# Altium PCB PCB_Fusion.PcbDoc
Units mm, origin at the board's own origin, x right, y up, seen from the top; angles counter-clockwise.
Board outline 25.02 x 45.09 mm, 2 copper layers (Top Layer, Bottom Layer); 48 components, 36 nets, 184 pads, 53 vias.
Unrouted connection lines stored in the file: 1.
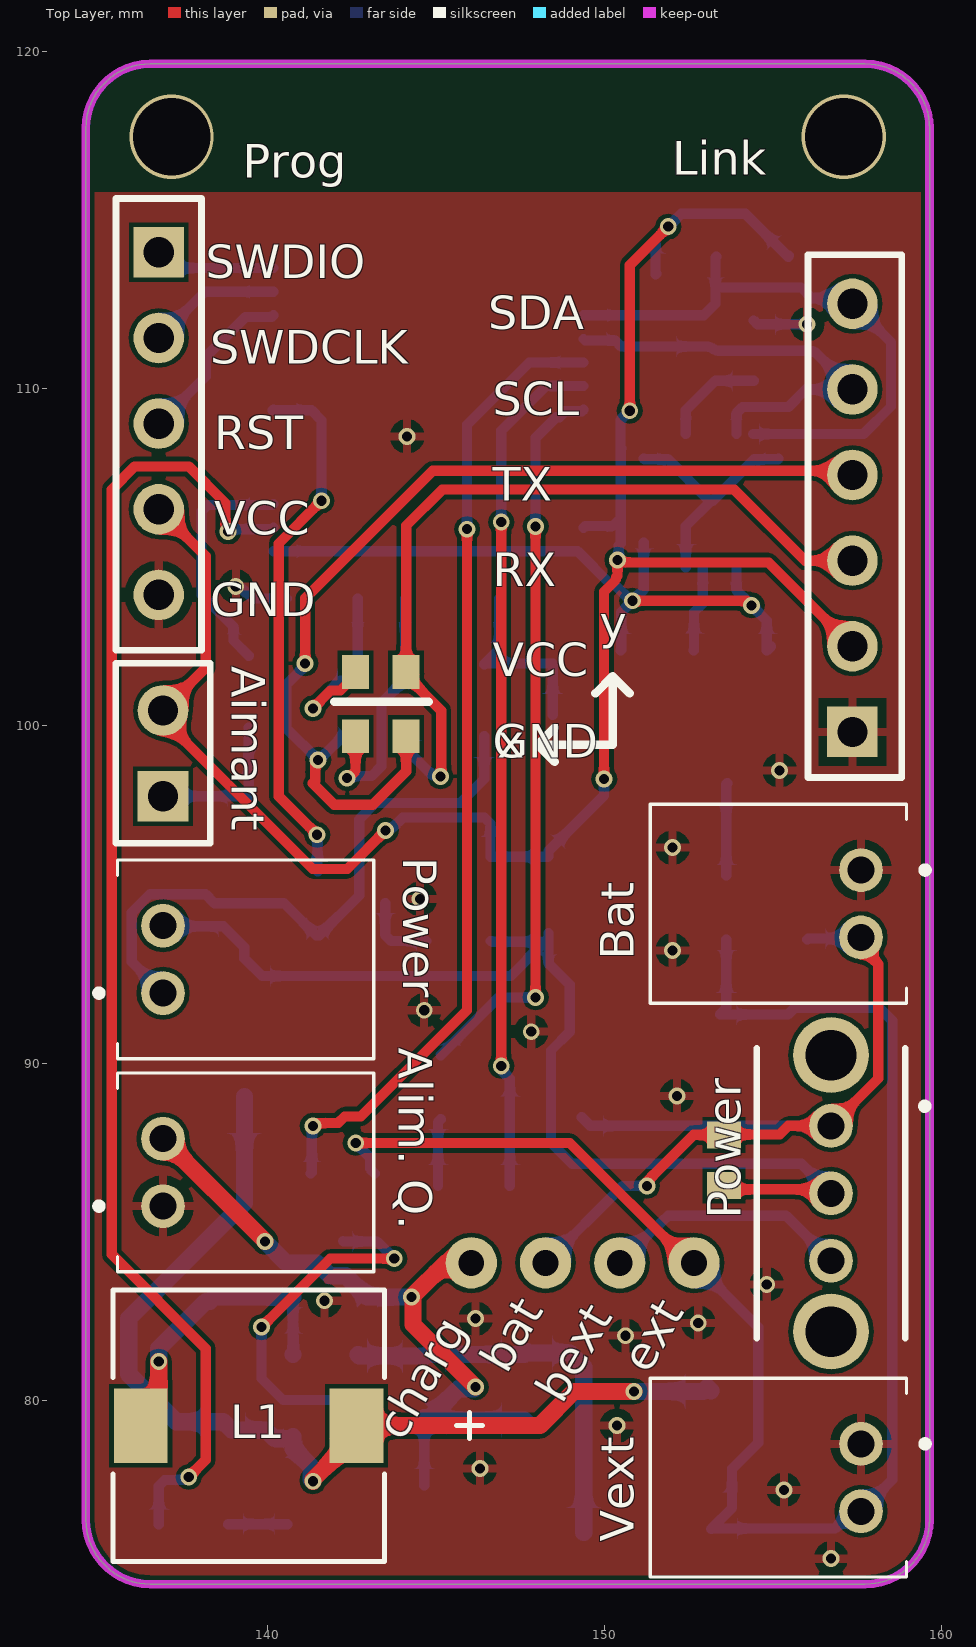
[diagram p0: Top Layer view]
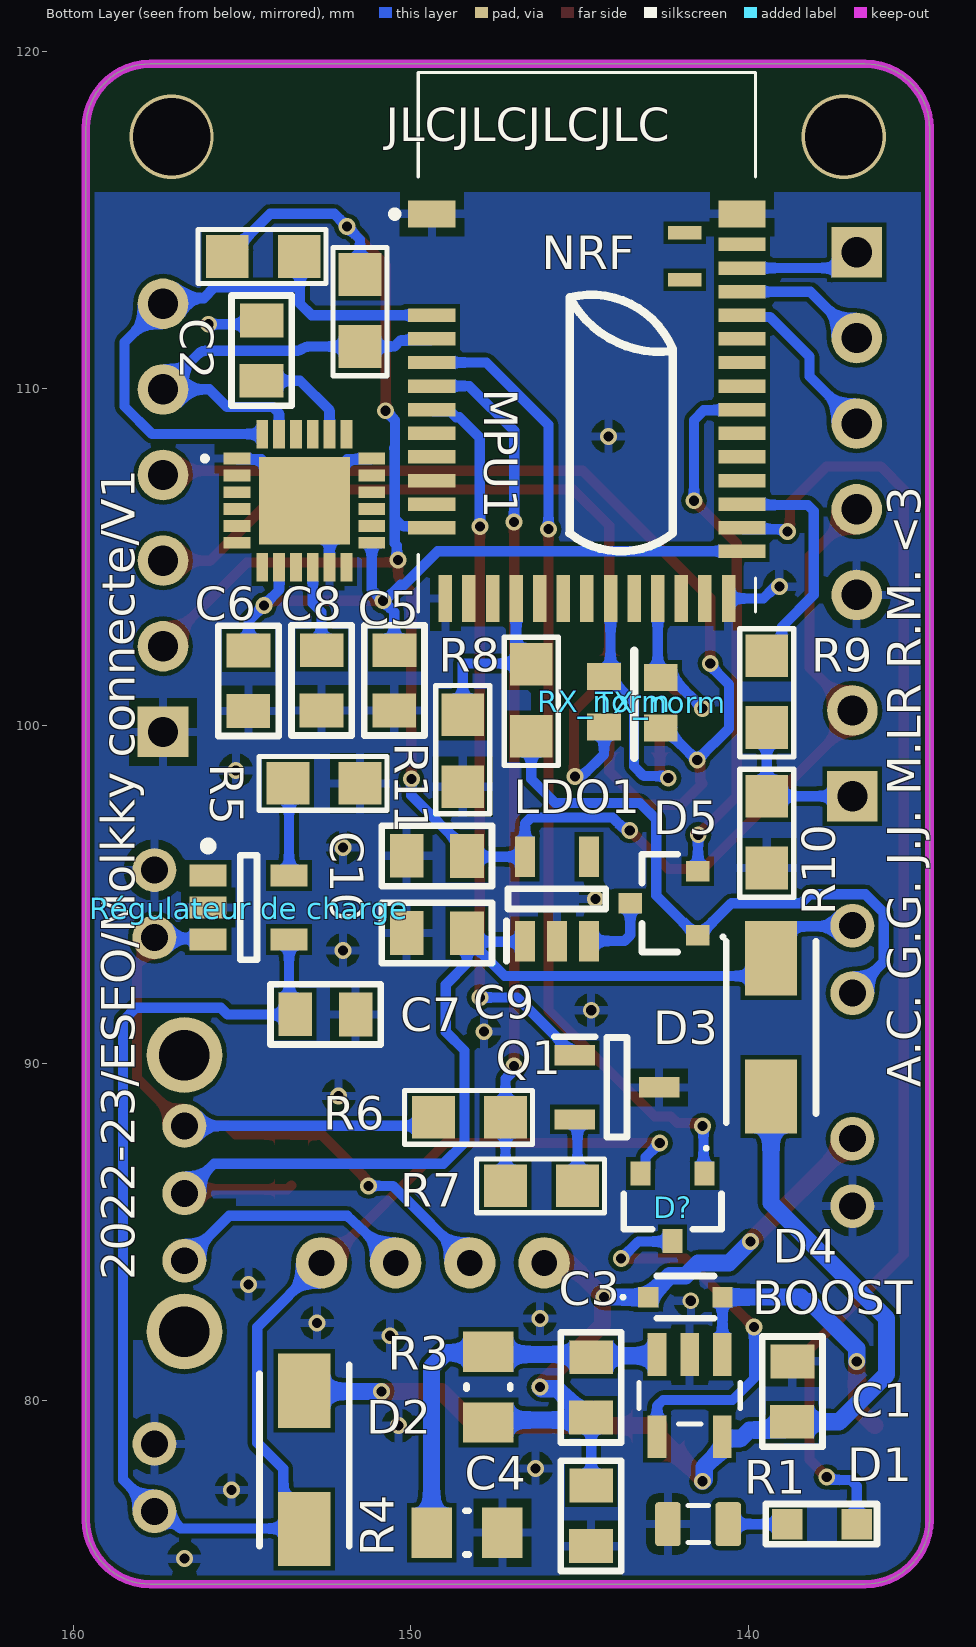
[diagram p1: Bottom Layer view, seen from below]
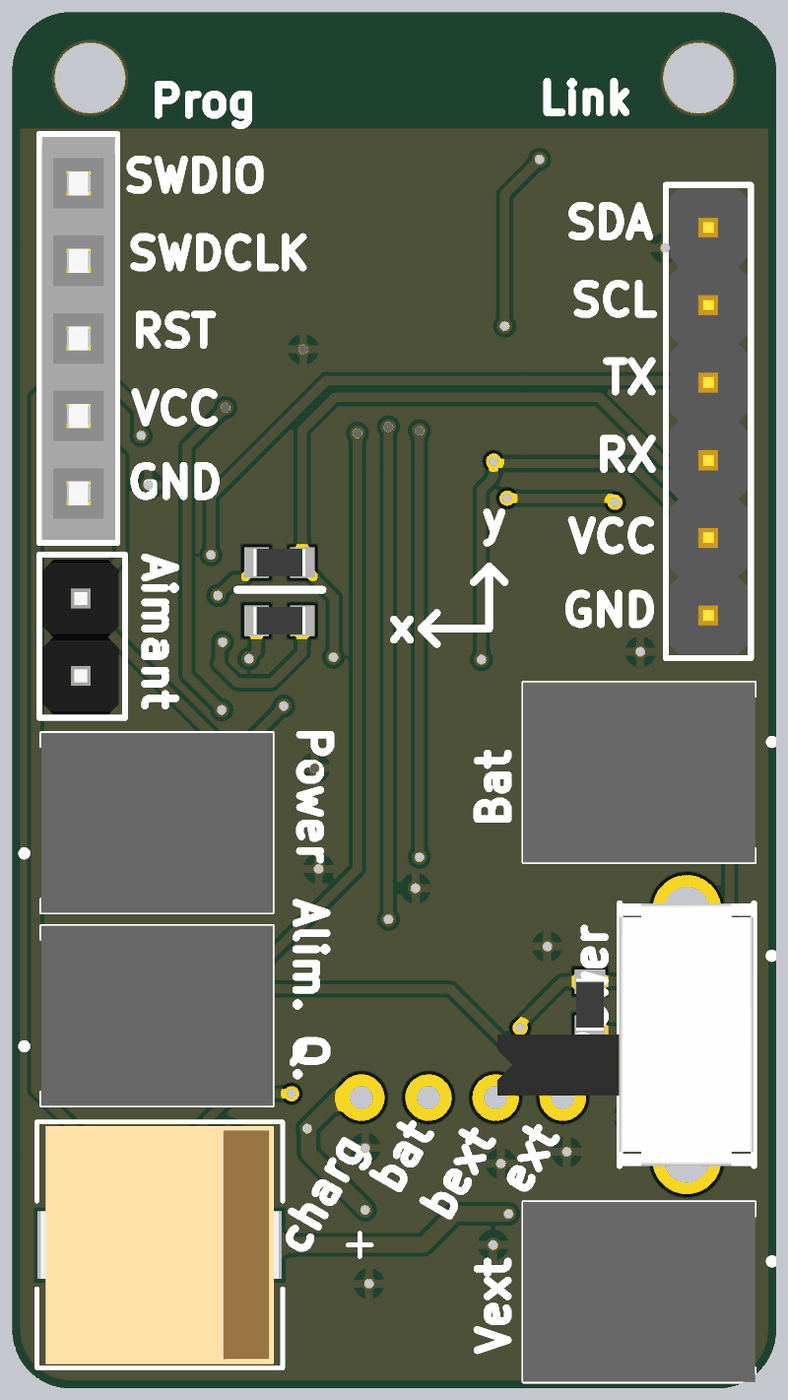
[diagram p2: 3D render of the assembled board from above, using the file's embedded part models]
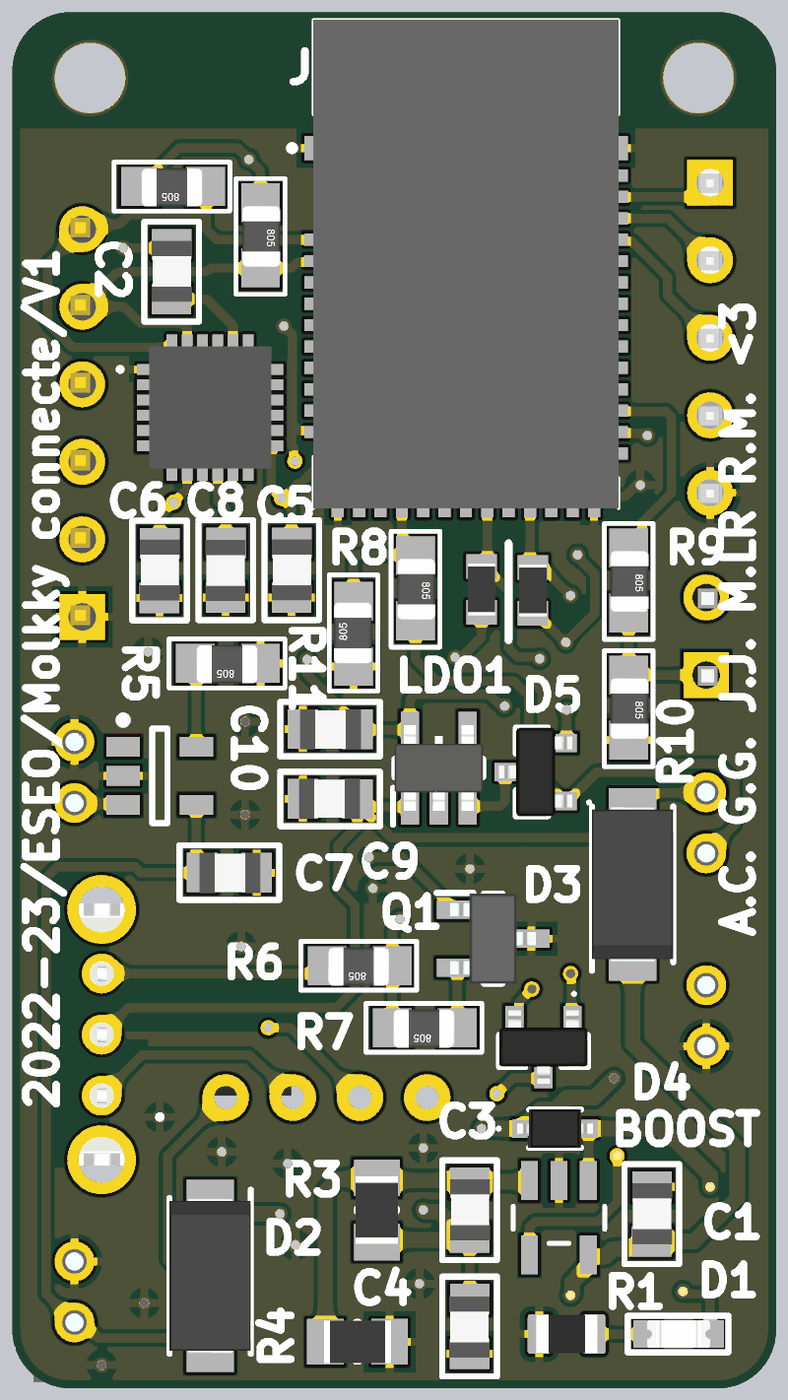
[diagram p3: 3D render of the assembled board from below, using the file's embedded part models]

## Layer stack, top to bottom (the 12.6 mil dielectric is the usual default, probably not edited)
Top Solder: solder mask 0.0102, Solder Resist, Dk 3.5
Top Layer: signal copper 0.0356
Dielectric 1: dielectric 0.32, FR-4, Dk 4.8
Bottom Layer: signal copper 0.0356
Bottom Solder: solder mask 0.0102, Solder Resist, Dk 3.5

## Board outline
134.62,76.454 134.62,117.729 cw(c136.525,117.729) 136.525,119.634 157.734,119.634 cw(c157.734,117.729) 159.639,117.729 159.639,76.454 cw(c157.734,76.454) 157.734,74.549 136.525,74.549 cw(c136.525,76.454)

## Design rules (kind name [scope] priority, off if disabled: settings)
Clearance [All] p1: gap=0.127 ignorepadtopadclearanceinfootprint=FALSE except(0.254: Arc-Via Track-Via Via-Via; 0.508: THPad-THPad)
PolygonConnect [All] p1: connectstyle=Relief reliefconductorwidth=0.254 reliefentries=4 polygonreliefangle="90 Angle" airgapwidth=0.254
RoutingVias [All] p1: holewidth=0.3 width=0.5 viastyle="Through Hole" minholewidth=0.762 minwidth=0.381 maxholewidth=1.016 maxwidth=0.762
SMDNeckDown [All] p1: percent=50.000
SolderMaskExpansion [All] p1: expansion=0.102 istentingtop=FALSE
Width [All] p1: maxlimit=0.508 minlimit=0.127 preferedwidth=0.305
30 further rules are at their usual default settings.

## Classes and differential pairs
component class Fusion: BOOST C1 C2 C3 C4 C5 C6 C7 C8 C9 C10 D1 D2 D3 D4 D5 L1 LDO1 Link MPU1 NRF Prog Q1 R1 R3 R4 R5 R6 R7 R8 R9 R10 R11

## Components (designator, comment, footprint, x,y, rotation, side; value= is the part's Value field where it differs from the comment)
Aimant "JUMPER2" BARRETTE_2_M_D 136.906,97.917 r90 top (schematic designator "Switch magnetique1")
"Alim. Q." "S2B-PH-K-S" S2BPHKS 136.906,85.757 r270 top (schematic designator Connecteur_Alim_Quille1)
Bat "S2B-PH-K-S" S2BPHKS 157.607,95.726 r90 top (schematic designator "Connecteur Bat")
BOOST "LM2735XMF" SOT95P285X110-5N 141.732,80.137 r270 bottom
C1 "CONDENSATEUR_CMS_CER_0805" CONDENSATEUR_CMS_0805 138.694,79.363 r90 bottom value=10uF
C2 "CONDENSATEUR_CMS_CER_0805" CONDENSATEUR_CMS_0805 154.432,110.236 r90 bottom value=2.2nF
C3 "CONDENSATEUR_CMS_CER_0805" CONDENSATEUR_CMS_0805 144.663,79.49 r90 bottom value=330pF
C4 "CONDENSATEUR_CMS_CER_0805" CONDENSATEUR_CMS_0805 144.653,77.47 r270 bottom value=10uF
C5 "CONDENSATEUR_CMS_CER_0805" CONDENSATEUR_CMS_0805 150.495,100.457 r90 bottom value=100nF
C6 "CONDENSATEUR_CMS_CER_0805" CONDENSATEUR_CMS_0805 154.823,100.445 r90 bottom value=10nF
C7 "CONDENSATEUR_CMS_CER_0805" CONDENSATEUR_CMS_0805 153.428,91.45 r180 bottom value=4.7uF
C8 "CONDENSATEUR_CMS_CER_0805" CONDENSATEUR_CMS_0805 152.644,102.247 r270 bottom value=100nF
C9 "CONDENSATEUR_CMS_CER_0805" CONDENSATEUR_CMS_0805 148.336,93.853 r0 bottom value=1uF
C10 "CONDENSATEUR_CMS_CER_0805" CONDENSATEUR_CMS_0805 150.126,96.149 r180 bottom value=4.7uF
D1 "LED_CMS_0805" LED_CMS_0805 136.779,76.327 r270 bottom
D2 "ES1D-E3_61T" DIOM5127X229N 153.162,78.232 r270 bottom
D3 "ES1D-E3_61T" DIOM5127X229N 139.319,91.059 r90 bottom
D4 "BAT165AX" BAT165AX 141.859,83.058 r180 bottom
D5 "BAT54C,215" BAT54C215 142.494,94.742 r90 bottom
D? "BAT54C,215" BAT54C215 142.24,85.725 r0 bottom
L1 "1234659" IND_123_4659_RSP 139.446,79.248 r180 top
LDO1 "TPS76333DBVT" SOT95P280X145-5N 145.669,94.869 r90 bottom
Link "BARRETTE_6 CONTACTS_1 RANGEE_MALE_DROITE" BARRETTE_6_M_D 157.353,99.822 r90 top (schematic designator "Connecteur link")
MPU1 "MPU-6050" MPU6050 153.162,106.68 r180 bottom
NRF "MDBT42Q-512KV2" MDBT42Q512KV2 144.78,111.379 r180 bottom
Power "OS102011MA1QN1" OS102011MA1QN1 156.718,86.138 r270 top (schematic designator "Interrupteur glissière?")
Power "S2B-PH-K-S" S2BPHKS 136.906,92.075 r270 top (schematic designator "Interrupteur Power")
Prog "BARRETTE_5 CONTACTS_1 RANGEE_FEMELLE_DROITE" BARRETTE_5_F_D 136.779,114.046 r270 top (schematic designator "Connecteur prog1")
"PULLUP SCL1" "RESISTANCE_CMS_0805" RESISTANCE_CMS_0805 151.511,113.386 r270 bottom value=10k
"PULLUP SDA1" "RESISTANCE_CMS_0805" RESISTANCE_CMS_0805 153.314,113.919 r0 bottom value=10k
Q1 "TSM2312CX_RFG" SOT95P280X130-3N 143.891,89.281 r180 bottom
R1 "Resistor 1K +/-5% 0805 125 mW" RESC0805(2012)_L 141.478,76.327 r180 bottom value=150
R2 "Resistor 4k7 +/-1% 0603 100 mW" RESC1608X55X25ML10T15 153.543,87.122 r270 top value=0
R3 "Resistor 10k +/-1% 0805 125 mW" RESC2013X50X35ML15T15 147.701,80.391 r270 bottom value=3.3k
R4 "Resistor 10k +/-1% 0805 125 mW" RESC2013X50X35ML15T15 148.336,76.073 r0 bottom value=10k
R5 "RESISTANCE_CMS_0805" RESISTANCE_CMS_0805 151.511,98.298 r0 bottom value=10k
R6 "RESISTANCE_CMS_0805" RESISTANCE_CMS_0805 147.193,88.392 r0 bottom value=100k
R7 "RESISTANCE_CMS_0805" RESISTANCE_CMS_0805 145.059,86.36 r0 bottom value=100k
R8 "RESISTANCE_CMS_0805" RESISTANCE_CMS_0805 146.431,101.829 r270 bottom value=100k
R9 "RESISTANCE_CMS_0805" RESISTANCE_CMS_0805 139.446,102.083 r270 bottom value=100
R10 "RESISTANCE_CMS_0805" RESISTANCE_CMS_0805 139.446,97.917 r270 bottom value=10k
R11 "RESISTANCE_CMS_0805" RESISTANCE_CMS_0805 148.463,98.196 r90 bottom value=100k
RX_inv "Resistor 4k7 +/-1% 0603 100 mW" RESC1608X55X25ML10T15 143.367,99.695 r0 top value=0
RX_norm "Resistor 4k7 +/-1% 0603 100 mW" RESC1608X55X25ML10T15 144.272,100.723 r90 bottom value=0
"Régulateur de charge" "MCP73831T-2DCI/OT" SOT-23-OT5_N 154.813,94.615 r180 bottom
TX_inv "Resistor 4k7 +/-1% 0603 100 mW" RESC1608X55X25ML10T15 143.367,101.6 r0 top value=0
TX_norm "Resistor 4k7 +/-1% 0603 100 mW" RESC1608X55X25ML10T15 142.587,100.689 r90 bottom value=0
Vext "S2B-PH-K-S" S2BPHKS 157.607,78.708 r90 top (schematic designator "Connecteur Vext")

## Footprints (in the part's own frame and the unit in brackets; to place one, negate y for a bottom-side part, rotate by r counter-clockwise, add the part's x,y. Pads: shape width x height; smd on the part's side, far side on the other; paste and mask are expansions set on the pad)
BARRETTE_2_M_D [mm] "BARRETTE 2 CONTACTS ; 1 RANGEE ; DROITE ; MALE ; ESPACEMENT BROCHES = 2.54 mm"
  rect 1.5x1.5 hole 0.9: 1(0,0)
  round 1.5 hole 0.9: 2(2.54,0)
  silkscreen extent -1.4,-1.4 3.94,1.4, body extent -1.3,-1.2 3.78,1.3, height 8.55
BARRETTE_5_F_D [mm] "BARRETTE 5 CONTACTS ; 1 RANGEE ; DROITE ; FEMELLE ; ESPACEMENT BROCHES = 2.54 mm"
  rect 1.5x1.5 hole 0.9: 1(0,0)
  round 1.5 hole 0.9: 2(2.54,0) 3(5.08,0) 4(7.62,0) 5(10.16,0)
  silkscreen extent -1.6,-1.27 11.8,1.27, body extent -1.5,-1.2 11.7,1.21, height 8.5
BARRETTE_6_M_D [mm] "BARRETTE 6 CONTACTS ; 1 RANGEE ; DROITE ; MALE ; ESPACEMENT BROCHES = 2.54 mm"
  rect 1.5x1.5 hole 0.9: 1(0,0)
  round 1.5 hole 0.9: 2(2.54,0) 3(5.08,0) 4(7.62,0) 5(10.16,0) 6(12.7,0)
  silkscreen extent -1.35,-1.46 14.15,1.32, body extent -1.22,-1.34 14.02,1.2, height 10.1
BAT54C215 [mm]
  rect 0.6x0.7 smd: 1(-0.95,-1) 2(0.95,-1) 3(0,1)
  silkscreen extent -1.45,-1.8 1.45,0.65, body extent -1.45,-1.2 1.45,1.2, height 0.95
BAT165AX [mm]
  rect 0.6x0.6 smd: 1(-1.1,0) 2(1.1,0)
  silkscreen extent -1.9,-0.62 0.85,0.62, body extent -1.24,-0.62 1.24,0.63, height 0.93
CONDENSATEUR_CMS_0805 [mm] "CONDENSATEUR CMS 0805 ; DIMENSIONS : 2mm x 1.25mm"
  rect 1x1.3 smd: 1(0,0) 2(1.79,-0.01)
  silkscreen extent -0.74,-0.9 2.53,0.89, body extent -0.09,-0.67 1.91,0.64, height 0.73
DIOM5127X229N [mm]
  rect 2.2x1.55 smd: 1(-2.05,0) 2(2.05,0)
  silkscreen extent -2.82,-1.33 2.55,1.33, body extent -2.55,-1.33 2.55,1.33, height 2.29
IND_123_4659_RSP [mil]
  rect 63x87 smd paste+0 mask+0: 1(-126,0) 2(126,0)
  silkscreen extent -273,-159 159,159, body extent -154,-154 154,154, height 199
LED_CMS_0805 [mm] "LED CMS 0805 ; DIMENSIONS : 2.0mm x 0.9mm"
  rect 0.9x0.9 smd: 1(0,0) 2(0,-2.062)
  silkscreen extent -0.6,-2.7 0.6,0.6, body extent -0.45,-2.06 0.45,0, height 0.85
MDBT42Q512KV2 [mm]
  rect 1.4x0.8 smd: 1(-4.6,3.8) 39(4.6,3.8)
  rect 1.4x0.4 smd: 2(-4.6,0.8) 3(-4.6,0.1) 4(-4.6,-0.6) 5(-4.6,-1.3) 6(-4.6,-2) 7(-4.6,-2.7) 8(-4.6,-3.4) 9(-4.6,-4.1) 10(-4.6,-4.8) 11(-4.6,-5.5) 25(4.6,-6.2) 26(4.6,-5.5) 27(4.6,-4.8) 28(4.6,-4.1) 29(4.6,-3.4) 30(4.6,-2.7) 31(4.6,-2) 32(4.6,-1.3) 33(4.6,-0.6) 34(4.6,0.1) 35(4.6,0.8) 36(4.6,1.5) 37(4.6,2.2) 38(4.6,2.9)
  rect 0.4x1.4 smd: 12(-4.2,-7.6) 13(-3.5,-7.6) 14(-2.8,-7.6) 15(-2.1,-7.6) 16(-1.4,-7.6) 17(-0.7,-7.6) 18(0,-7.6) 19(0.7,-7.6) 20(1.4,-7.6) 21(2.1,-7.6) 22(2.8,-7.6) 23(3.5,-7.6) 24(4.2,-7.6)
  rect 1x0.4 smd: 40(2.9,3.25) 41(2.9,1.85)
  silkscreen extent -5.8,-8 5,8, body extent -5,-8 5,8, height 2.3
MPU6050 [mm]
  rect 0.8x0.35 smd: 1(-2,1.25) 2(-2,0.75) 3(-2,0.25) 4(-2,-0.25) 5(-2,-0.75) 6(-2,-1.25) 13(2,-1.25) 14(2,-0.75) 15(2,-0.25) 16(2,0.25) 17(2,0.75) 18(2,1.25)
  rect 0.35x0.85 smd: 7(-1.25,-1.975) 8(-0.75,-1.975) 9(-0.25,-1.975) 10(0.25,-1.975) 11(0.75,-1.975) 12(1.25,-1.975) 19(1.25,1.975) 20(0.75,1.975) 21(0.25,1.975) 22(-0.25,1.975) 23(-0.75,1.975) 24(-1.25,1.975)
  rect 2.7x2.6 smd: 25(0,0)
  silkscreen extent -3,1.2 -2.9,1.3, body extent -2,-2 2,2, height 0.88
OS102011MA1QN1 [mm]
  round 1.3 hole 0.8: 1(-2,0) 2(0,0) 3(2,0)
  round 2.25 hole 1.5: 4(-4.1,0) 5(4.1,0)
  silkscreen extent -4.3,-2.2 4.3,2.88, body extent -4.3,-6.22 4.3,2.18, height 4.59
RESC0805(2012)_L [mm] "Chip Resistor, Body 2.0x1.3mm, IPC High Density"
  rrect25% 0.76x1.3 smd: 1(-0.9,0) 2(0.89,0)
  silkscreen extent -0.3,-0.55 0.3,0.55, body extent -1,-0.62 1,0.63, height 0.6
RESC1608X55X25ML10T15 [mm] "Chip Resistor, 2-Leads, Body 1.70x0.90mm, IPC Low Density"
  rect 0.8x1 smd: 1(-0.75,0) 2(0.75,0)
  body extent -0.85,-0.45 0.85,0.45, height 0.55
RESC2013X50X35ML15T15 [mm] "Chip Resistor, 2-Leads, Body 2.2x1.4mm, IPC Low Density"
  rect 1.2x1.5 smd: 1(-1.05,0) 2(1.05,0)
  silkscreen extent -0.05,-0.65 0.05,0.65, body extent -1.1,-0.7 1.1,0.7, height 0.5
RESISTANCE_CMS_0805 [mil] "RESISTANCE CMS 0805 ; DIMENSIONS : 2mm x 1.25mm"
  rect 50x50 smd: 1(0,0) 2(84,0)
  silkscreen extent -31,-31 118,31, body extent 4,-24 83,26, height 31
S2BPHKS [mm]
  round 1.3 hole 0.8: 1(0,0) 2(-2,0)
  silkscreen extent -3.95,-2 1.95,6.25, body extent -3.95,-1.35 1.95,6.25, height 4.9
SOT95P280X130-3N [mm]
  rect 1.2x0.6 smd: 1(-1.25,0.95) 2(-1.25,-0.95) 3(1.25,0)
  silkscreen extent -1.85,-1.47 0.3,1.5, body extent -1.4,-1.47 1.4,1.47, height 1.3
SOT95P280X145-5N [mm]
  rect 1.2x0.6 smd: 1(-1.25,0.95) 2(-1.25,0) 3(-1.25,-0.95) 4(1.25,-0.95) 5(1.25,0.95)
  silkscreen extent -1.85,-1.45 0.3,1.5, body extent -1.4,-1.45 1.4,1.45, height 1.2
SOT95P285X110-5N [mil]
  rect 50x22 smd: 1(-48,38) 2(-48,0) 3(-48,-38) 4(48,-38) 5(48,38)
  silkscreen extent -15,-59 33,59
SOT-23-OT5_N [mm] "SOT23, 5-Leads, Body 2.9x1.6mm, Pitch 0.95mm, Lead Span 2.7mm, IPC Medium Density"
  rect 1.1x0.65 smd: 1(-1.2,0.95) 2(-1.2,0) 3(-1.2,-0.95) 4(1.2,-0.95) 5(1.2,0.95)
  silkscreen extent -1.33,-1.55 0.25,1.95, body extent -0.9,-1.55 0.9,1.55, height 1.45

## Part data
Aimant: library part CMP-039-0004-1, "BARRETTE 2 CONTACTS 1 RANGEE MALE DROITE"
"Alim. Q." Bat Power Vext: "Connector", Manufacturer_Name="JST (JAPAN SOLDERLESS TERMINALS)"
BOOST: "Integrated Circuit", Manufacturer_Name="Texas Instruments"
C1 C2 C3 C4 C5 C6 C7 C8 C9 C10: library part CMP-038-0003-1, "CONDENSATEUR CMS CERAMIQUE 0805"
D1: library part CMP-024-0003-1, "LED CMS 0805"
D2 D3: "Diode", Arrow Part Number=ES1D-E3/61T, Manufacturer_Name=Vishay, Mouser Part Number=625-ES1D-E3
D4: "Schottky Diode", Manufacturer_Name=Nexperia, Mouser Part Number=771-BAT165AX
D5 D?: "Schottky Diode", Manufacturer_Name=Nexperia, Mouser Part Number=771-BAT54C-T/R
L1: "No Description Available", Mfr_Name="RS Pro"
LDO1: "Integrated Circuit", Manufacturer_Name="Texas Instruments", Mouser Part Number=595-TPS76333DBVT
Link: library part CMP-039-0125-1, "BARRETTE 6 CONTACTS 1 RANGEE MALE DROITE"
MPU1: "Integrated Circuit", Manufacturer_Name=TDK, Mouser Part Number=410-MPU-6050
NRF: "Integrated Circuit", Manufacturer_Name=Raytac
Power: "Switch", Manufacturer_Name="C & K COMPONENTS", Mouser Part Number=611-OS102011MA1QN1
Prog: library part CMP-039-0118-1, "BARRETTE 5 CONTACTS 1 RANGEE FEMELLE DROITE"
"PULLUP SCL1" "PULLUP SDA1" R5 R6 R7 R8 R9 R10 R11: library part CMP-037-0001-1, "RESISTANCE CMS 0805"
Q1: "MOSFET (N-Channel)", Arrow Part Number="TSM2312CX RFG", Manufacturer_Name="Taiwan Semiconductor", Mouser Part Number=821-TSM2312CXRFG
R1: library part CMP-009-00118-3, "Chip Resistor, 1 kOhms, +/-5%, 125 mW, -55 to 155 degC, 0805", Case/Package=0805, Max Operating Temperature=155°C, Min Operating Temperature=-55°C, Power=125mW, Tolerance=5%
R2 RX_inv RX_norm TX_inv TX_norm: library part CMP-009-00031-5, "Chip Resistor, 4.7 KOhm, +/- 1%, 0.1 W, -55 to 155 degC, 0603 (1608 Metric)", Case/Package=0603, Max Operating Temperature=155°C, Min Operating Temperature=-55°C, Power=100mW, Tolerance=1%
R3 R4: library part CMP-009-00018-5, "Chip Resistor, 10 KOhm, +/- 1%, 125 mW, -55 to 155 degC, 0805 (2012 Metric)", Case/Package=0805, Max Operating Temperature=155°C, Min Operating Temperature=-55°C, Power=125mW, Tolerance=1%, Voltage Rating=150V
"Régulateur de charge": library part CMP-045-0000-1, "Miniature Single-Cell, Fully Integrated Li-Ion, Li-Polymer Charge Management Controller, 4.2V, 5-Pin SOT-23, Industrial Temperature, Tape and Reel", Manufacturer=Microchip

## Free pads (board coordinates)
  round 1.524 hole 0.762: 2(150.453,84.074) 3(148.251,84.074) 5(146.05,84.074) 6(152.654,84.074)

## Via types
v1: diameter 0.5, hole 0.3, Top Layer to Bottom Layer, 51 vias
v2: diameter 2.5, hole 2.3, Top Layer to Bottom Layer, 2 vias

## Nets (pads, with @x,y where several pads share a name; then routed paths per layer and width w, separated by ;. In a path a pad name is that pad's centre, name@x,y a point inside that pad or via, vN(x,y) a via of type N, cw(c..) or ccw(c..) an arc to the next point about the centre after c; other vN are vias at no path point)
Aimant: NRF.27 R9.1 | length 7.1
  Bottom Layer w0.305: R9.1 138.996,102.533 138.996,102.939 138.049,103.886 138.049,106.374 138.228,106.553 140.154,106.553 NRF.27
"EN lecture bat": NRF.6 Q1.1 | length 21.9
  Top Layer w0.305: v1(147.955,91.948) v1(147.955,105.918)
  Bottom Layer w0.305: Q1.1 146.858,91.948 v1(147.955,91.948) ; v1(147.955,105.918) 147.955,108.549 148.564,109.158 148.659,109.158 148.832,109.331 149.332,109.331 NRF.6
EN_Alim_quilles: D?.1 NRF.4 | length 29
  Top Layer w0.305: v1(141.351,88.138) 141.438,88.225 142.103,88.225 142.295,88.417 142.773,88.417 145.923,91.567 v1(145.923,105.835)
  Bottom Layer w0.305: D?.1 141.32,86.756 141.32,88.107 v1(141.351,88.138) ; v1(145.923,105.835) 145.923,108.937 147.765,110.779 NRF.4
GND: "Alim. Q..1" "Régulateur de charge.2" Bat.1 BOOST.2 C1.2 C2.2 C4.2 C5.1 C6.1 C7.2 C8.2 C9.2 C10.1 LDO1.2 Link.1 MPU1.1 MPU1.11 MPU1.18 MPU1.25 NRF.1 NRF.12 NRF.24 NRF.39 Prog.5 Q1.3 R1.1 R4.1 R5.1 R10.2 R11.1 Vext.1 | length 10.6
  Bottom Layer w0.305: v1(139.065,104.14) 139.189,104.14 139.55,103.779 NRF.24 ; MPU1.18 151.185,107.907 151.885,107.907 153.112,106.68 MPU1.25 ; MPU1.11 152.412,105.93 MPU1.25 ; C2.2 154.536,111.912 v1(156.009,111.912) ; MPU1.1 155.139,107.907 154.439,107.907 153.212,106.68 MPU1.25
  other v1: 156.718,75.311 155.321,77.343 146.304,77.978 150.368,79.248 150.622,81.915 152.781,82.296 146.177,82.423 141.7,82.952 154.813,83.439 152.146,89.027 147.828,90.932 144.653,91.567 152.019,93.345 144.526,94.869 152.019,96.393 155.194,98.679 144.145,108.585
"Lecture Vbat": NRF.5 R6.1 R7.2 | length 25.5
  Top Layer w0.305: v1(146.939,89.916) v1(146.939,106.045)
  Bottom Layer w0.305: v1(146.939,89.916) 146.939,89.792 147.193,89.538 R6.1 R7.2 ; v1(146.939,106.045) 146.939,108.754 148.264,110.079 NRF.5
LED: D1.1 NRF.26 | length 39.2
  Top Layer w0.305: v1(137.668,77.724) 138.176,78.232 138.176,81.534 135.382,84.328 135.382,107.009 136.069,107.696 137.668,107.696 138.76,106.604 138.76,105.842 v1(138.836,105.766)
  Bottom Layer w0.305: D1.1 136.779,77.458 136.958,77.637 137.581,77.637 v1(137.668,77.724) ; v1(138.836,105.766) 138.902,105.831 140.132,105.831 NRF.26
NetBOOST_1: BOOST.1 D4.2 L1.2 | length 8.8
  Top Layer w0.508: L1.2 136.779,79.781 v1(136.779,81.147)
  Bottom Layer w0.305: BOOST.1@140.763,81.36 D4.2@140.763,83.054
  Bottom Layer w0.508: v1(136.779,81.147) 136.779,81.534 138.176,82.931 138.303,82.931 138.43,83.058 D4.2 D4.2@140.763,83.054 ; BOOST.1@140.763,81.36 BOOST.1
NetBOOST_3: BOOST.3 C3.2 R3.1 R4.2 | length 11.9
  Bottom Layer w0.508: BOOST.3 142.697,81.343 142.723,81.318 144.615,81.318 C3.2 144.733,81.36 147.621,81.36 R3.1 147.735,81.407 148.971,81.407 149.386,80.992 R4.2
NetBOOST_4: BOOST.4 D?.3 | length 12.2
  Top Layer w0.3: v1(139.827,82.169) 141.859,84.201 v1(143.764,84.201)
  Bottom Layer w0.3: v1(139.827,82.169) 139.827,80.645 140.462,80.01 142.521,80.01 142.697,79.834 BOOST.4 ; D?.3 142.256,84.709 143.256,84.709 v1(143.764,84.201)
NetBOOST_5: BOOST.5 C1.1 D2.1 D3.1 L1.1 | length 30.1
  Top Layer w0.508: v1(141.351,77.597) 141.351,77.648 142.646,78.943 L1.1 148.082,79.248 149.098,80.264 v1(150.876,80.264)
  Bottom Layer w0.508: D3.1 139.319,85.852 135.89,82.423 135.89,80.772 137.299,79.363 C1.1 138.94,79.117 139.958,79.117 140.208,78.867 140.741,78.867 BOOST.5@140.767,78.892 ; BOOST.5 BOOST.5@140.767,78.892 ; v1(141.351,77.597) 141.302,77.646 141.302,78.027 140.767,78.562 BOOST.5@140.767,78.892 ; v1(150.876,80.264) 152.926,80.264 153.053,80.391 D2.1
NetC2_1: C2.1 MPU1.20 | length 3.1
  Bottom Layer w0.305: MPU1.20 152.412,109.359 153.289,110.236 C2.1
NetC8_1: C8.1 MPU1.10 | length 2.6
  Bottom Layer w0.305: C8.1 152.654,102.257 152.654,103.378 152.912,103.636 MPU1.10
NetD1_2: D1.2 R1.2 | length 1.7
  Bottom Layer w0.305: D1.2 R1.2
NetD5_1: D5.1 Power.1@136.906,92.075 R8.2 | length 18.5
  Bottom Layer w0.305: Power.1@136.906,92.075 135.977,93.004 135.977,94.46 136.521,95.004 138.168,95.004 138.43,94.742 140.494,94.742 141.444,93.792 D5.1 141.544,93.792 142.723,94.971 142.723,97.227 143.209,97.714 145.72,97.714 146.431,98.425 R8.2
NetD5_3: D5.3 LDO1.3 | length 2.2
  Bottom Layer w0.305: D5.3 143.494,93.798 143.673,93.619 LDO1.3
NetQ1_2: Q1.2 R7.1 | length 2
  Bottom Layer w0.305: R7.1 145.059,88.249 Q1.2
NetR5_2: "Régulateur de charge.5" R5.2 | length 2.7
  Bottom Layer w0.305: 153.613,95.565 153.613,98.266 R5.2
NetR9_2: Aimant.1 R9.2 R10.1 | length 4.6
  Bottom Layer w0.305: Aimant.1 R10.1 R9.2
Power: NRF.15 R8.1 R11.2 | length 5.7
  Bottom Layer w0.305: R8.1 R8.1@146.456,101.854 ; NRF.15 146.88,102.278 R8.1@146.456,101.854 ; R11.2 148.463,101.854 R8.1@146.456,101.854
RESET: NRF.35 Prog.3 | length 5.1
  Bottom Layer w0.305: Prog.3 138.176,110.363 138.176,110.95 139.358,112.131 140.132,112.131 NRF.35
RX: NRF.19 RX_inv.1 RX_norm.2 | length 7.8
  Top Layer w0.305: v1(142.367,98.45) 142.392,98.45 142.617,98.675 RX_inv.1
  Bottom Layer w0.305: v1(142.367,98.45) 142.429,98.512 143.089,98.512 143.383,98.806 143.383,100.711 143.41,100.711 144.08,101.381 NRF.19
RX_out: Link.3 RX_norm.1 TX_inv.2 | length 24.4
  Top Layer w0.305: v1(145.136,98.501) 145.161,98.527 145.161,100.456 144.117,101.5 TX_inv.2 144.117,105.945 145.182,107.01 153.848,107.01 155.956,104.902 Link.3
  Bottom Layer w0.305: RX_norm.1 144.272,99.162 144.896,98.538 145.099,98.538 v1(145.136,98.501)
SCL: "PULLUP SCL1.2" Link.5 MPU1.23 NRF.3 | length 12.9
  Bottom Layer w0.305: NRF.3 149.428,111.431 150.316,111.431 150.495,111.252 153.028,111.252 cw(c153.028,110.947) 153.187,111.207 153.249,111.17 ccw(c153.407,111.43) 153.407,111.125 156.084,111.125 cw(c156.084,110.82) 156.299,111.036 Link.5 155.977,109.982 155.452,109.457 154.091,109.457 153.912,109.278 MPU1.23
SDA: "PULLUP SDA1.1" Link.6 MPU1.24 NRF.2 | length 17.7
  Bottom Layer w0.305: NRF.2 152.946,112.179 153.289,112.522 153.289,113.03 ; 153.314,113.919 153.289,113.894 153.289,113.03 ; MPU1.24 157.677,108.655 158.496,109.474 158.496,111.379 Link.6 157.187,112.688 156.146,112.688 155.829,113.005 153.314,113.005 153.289,113.03
Shutdown: D5.2 NRF.31 | length 16
  Top Layer w0.305: v1(141.478,96.774) 140.335,97.917 140.335,105.41 v1(141.605,106.68)
  Bottom Layer w0.305: NRF.31@140.164,109.363 NRF.31 140.196,109.363 141.312,109.363 141.605,109.07 v1(141.605,106.68) ; v1(141.478,96.774) 141.486,96.766 141.486,95.7 D5.2
SWDCLK: NRF.36 Prog.2 | length 4
  Bottom Layer w0.305: Prog.2 138.152,112.879 NRF.36
SWDIO: NRF.37 Prog.1 | length 3.6
  Bottom Layer w0.305: Prog.1 137.246,113.579 NRF.37
TX: NRF.21 TX_inv.1 TX_norm.2 | length 5.8
  Top Layer w0.305: v1(141.351,100.52) 141.883,101.052 142.169,101.052 142.617,101.5 TX_inv.1
  Bottom Layer w0.305: v1(141.351,100.52) 142.177,101.346 142.494,101.346 TX_norm.2 142.68,101.532 NRF.21
TX_out: Link.4 RX_inv.2 TX_norm.1 | length 30
  Top Layer w0.305: v1(141.122,101.854) 141.122,103.784 144.907,107.569 157.226,107.569 Link.4 ; v1(141.507,98.992) 141.42,98.904 141.42,98.367 141.351,98.298 141.986,97.663 143.129,97.663 144.117,98.651 RX_inv.2
  Bottom Layer w0.305: v1(141.122,101.854) 141.122,101.786 140.564,101.227 140.564,99.935 v1(141.507,98.992) 141.54,98.992 142.487,99.939 TX_norm.1
Vbat_Ext: pad.2 Power.3 | length 7.4
  Bottom Layer w0.305: pad.2@150.368,84.074 151.892,85.471 155.385,85.471 Power.3
Vbat_In: "Régulateur de charge.3" Bat.2 pad.3 Power.1@156.718,88.138 R2.1 R6.2 | length 25.7
  Top Layer w0.3: v1(151.257,86.36) 151.257,86.487 151.638,86.868
  Top Layer w0.305: 151.638,86.868 152.642,87.872 R2.1 153.555,87.884 155.194,87.884 155.448,88.138 156.718,88.138 158.122,89.542 158.122,92.941 157.607,93.457 Bat.2
  Bottom Layer w0.3: pad.3 150.537,86.36 v1(151.257,86.36)
  Bottom Layer w0.305: R6.2 149.581,88.138 Power.1@156.718,88.138 ; 156.013,93.665 156.044,93.695 157.576,93.695 Bat.2
Vbat_Out: C9.1 D3.2 LDO1.1 Power.2 R2.2 | length 33.1
  Top Layer w0.305: R2.2 153.66,86.255 156.601,86.255 Power.2@156.718,86.138
  Bottom Layer w0.305: Power.2@136.906,94.075 136.924,94.057 138.696,94.057 139.319,93.434 D3.2 139.845,92.583 147.216,92.583 148.157,93.524 C9.1@148.336,93.703 ; LDO1.1 146.665,93.619 146.685,93.599 C9.1@148.082,93.599 ; C9.1 C9.1@148.336,93.703 ; Power.2@156.718,86.138 155.84,87.016 149.037,87.016 148.412,87.641 148.412,90.373 148.971,90.932 148.971,92.329 148.336,92.964 C9.1@148.336,93.703
VCC: "PULLUP SCL1.1" "PULLUP SDA1.2" Aimant.2 C10.2 LDO1.5 Link.2 NRF.11 Prog.4 | length 59.7
  Top Layer w0.305: Prog.4 138.176,105.029 138.176,101.727 Aimant.2 136.906,100.203 141.351,95.758 142.367,95.758 v1(143.51,96.901) ; v1(149.987,98.425) 149.987,103.986 150.342,104.342 150.342,104.414 150.385,104.456 v1(150.385,104.925) ; v1@150.305,104.845 154.87,104.845 Link.2 ; v1(150.749,109.347) 150.749,113.665 v1(151.892,114.808)
  Bottom Layer w0.305: v1(143.51,96.901) 143.597,96.988 143.724,96.988 144.018,97.282 146.44,97.282 146.619,97.103 LDO1.5 148.316,96.119 C10.2 148.336,96.289 149.987,97.94 v1(149.987,98.425) ; NRF.11 149.428,105.927 150.25,105.927 150.472,106.149 150.472,108.221 150.472,109.07 v1(150.749,109.347) ; v1(150.385,104.925) 150.422,104.962 150.422,105.349 150.483,105.41 150.483,106.149 150.483,108.221 150.495,108.233 ; 151.536,113.411 151.511,113.386 151.511,114.427 v1(151.892,114.808) 152.273,115.189 154.178,115.189 155.448,113.919 155.473,113.944
VCC_MPU: C5.2 C6.2 MPU1.8 MPU1.13 NRF.25 | length 21.3
  Top Layer w0.305: v1(150.829,103.712) 154.225,103.712 v1(154.363,103.574)
  Bottom Layer w0.305: NRF.25 149.202,105.179 150.192,104.189 150.305,104.189 150.783,103.712 v1(150.829,103.712) ; C5.2 150.495,102.257 150.495,103.378 v1(150.829,103.712) ; MPU1.13 151.162,104.045 v1(150.829,103.712) ; MPU1.8 153.912,104.025 v1(154.363,103.574) 154.813,103.124 C6.2 C6.2@154.94,102.362
Vchargement: "Alim. Q..2" C3.1 C4.1 D4.1 pad.5 R3.2 | length 22
  Top Layer w0.508: 136.906,87.757 136.906,87.744 139.929,84.722 v1(139.929,84.709) ; pad.5 145.288,84.074 v1(144.272,83.058) 144.321,83.009 144.321,82.247 v1(146.177,80.391)
  Bottom Layer w0.305: C4.1 C3.1@144.653,79.48
  Bottom Layer w0.508: v1(139.929,84.709) 140.564,84.074 141.478,84.074 141.859,83.693 142.324,83.693 D4.1 v1(144.272,83.058) ; C3.1@144.653,79.48 144.717,79.416 147.627,79.416 R3.2 ; C3.1 144.813,79.49 145.665,80.342 146.128,80.342 v1(146.177,80.391)
Vext: "Régulateur de charge.4" C7.1 D2.2 D?.2 pad.6 Vext.2 | length 49.1
  Top Layer w0.305: v1(142.621,87.63) 148.975,87.63 152.531,84.074 pad.6
  Bottom Layer w0.305: v1(142.621,87.63) 143.042,87.209 143.042,86.873 D?.2 ; pad.6 154.559,82.169 154.559,78.74 153.785,77.966 153.785,76.805 D2.2@153.18,76.2 ; D2.2 D2.2@153.18,76.2 ; 153.613,93.665 153.613,91.635 C7.1 153.438,91.44 155.436,91.44 155.639,91.642 158.155,91.642 158.536,91.261 158.536,77.637 Vext.2 157.338,76.708 156.83,76.2 D2.2@153.18,76.2
pads on no net: "Régulateur de charge.1" LDO1.4 MPU1.2 MPU1.3 MPU1.4 MPU1.5 MPU1.6 MPU1.7 MPU1.9 MPU1.12 MPU1.14 MPU1.15 MPU1.16 MPU1.17 MPU1.19 MPU1.21 MPU1.22 NRF.7 NRF.8 NRF.9 NRF.10 NRF.13 NRF.14 NRF.16 NRF.17 NRF.18 NRF.20 NRF.22 NRF.23 NRF.28 NRF.29 NRF.30 NRF.32 NRF.33 NRF.34 NRF.38 NRF.40 NRF.41 Power.4 Power.5
copper on no net:
  other v2: 137.16,117.475 157.099,117.475

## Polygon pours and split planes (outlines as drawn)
GND on Top Layer "TOP_GND" (solid, remove dead copper, pour order 1): 134.62,119.634 134.62,74.549 159.639,74.549 159.639,119.634
GND on Bottom Layer "BTM_GND" (solid, remove dead copper, pour order 0): 134.62,119.634 134.62,74.549 159.639,74.549 159.639,119.634

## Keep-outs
Keep-Out Layer:
  the board outline again, w0.254

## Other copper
Top Layer:
  pour cut-out: 134.62,119.634 159.639,119.634 159.639,115.824 134.62,115.824
Bottom Layer:
  pour cut-out: 156.718,86.138 156.559,85.979 155.194,85.979 155.194,85.662 156.845,84.011 156.845,81.788 158.496,81.788 158.623,81.915 158.623,86.868 156.972,86.868 156.845,86.741
  pour cut-out: 156.897,91.642 158.155,91.642 158.536,91.261 158.496,91.221 158.496,87.249 156.845,87.249 156.718,87.376
  pour cut-out: 146.939,101.473 146.431,100.965 146.431,98.425 146.05,98.425 145.415,97.79 143.51,99.695 143.51,102.489 144.272,103.251 144.495,103.028 146.88,103.028
  pour cut-out: 150.114,111.252 150.241,111.125 154.305,111.125 154.305,110.363 152.019,108.077 150.622,108.077 150.622,108.839 150.114,109.347
  pour cut-out: 148.463,87.63 149.86,86.233 156.845,86.233 156.972,86.36 156.718,86.614 156.718,88.138 148.717,88.138
  pour cut-out: 134.62,119.634 134.62,115.824 159.639,115.824 159.639,119.634

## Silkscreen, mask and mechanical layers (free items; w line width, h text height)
Top Overlay:
  lines w0.254: 141.986,100.711 144.78,100.711 ; 148.526,98.933 148.018,99.441 ; 148.526,99.949 148.018,99.441 ; 149.733,100.965 150.241,101.473 150.749,100.965 ; 150.177,99.441 148.018,99.441 ; 150.241,99.441 150.241,101.219
  text "SWDIO" at 138.176,113.284 h1
  text "SDA" at 146.558,111.76 h1
  text "SWDCLK" at 138.303,110.744 h1
  text "SCL" at 146.685,109.22 h1
  text "RST" at 138.43,108.204 h1
  text "TX" at 146.685,106.68 h1
  text "VCC" at 138.43,105.664 h1
  text "RX" at 146.685,104.14 h1
  text "GND" at 138.303,103.251 h1
  text "y" at 149.86,102.568 h1
  text "VCC" at 146.685,101.473 h1
  text "GND" at 146.685,99.06 h1
  text "x" at 146.812,99.06 h1
  text "bat" at 147.1,80.738 h1 r60
  text "ext" at 151.291,80.738 h1 r60
  text "bext" at 148.751,79.849 h1 r60
  text "charg" at 144.017,78.746 h1 r60
Bottom Overlay:
  lines w0.254: 142.232,111.123 ccw(c142.621,114.109) 145.288,112.712 ; 142.24,105.71 ccw(c143.764,107.632) 145.296,105.716 ; 142.24,105.727 142.24,111.123 ; 142.24,111.188 cw(c144.653,110.172) 145.288,112.712 ; 143.383,99.06 143.383,102.235 ; 145.288,105.727 145.288,112.712
  text "JLCJLCJLCJLC" at 150.749,117.348 h1
  text "A.C. G.G. J.J. M.LR R.M. <3" at 134.874,89.281 h1 r270
  text "2022-23/ESEO/Molkky connecte/V1" at 158.194,83.566 h1 r270
Mechanical 13:
  rectangle: 128.651,70.523 158.651,120.523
